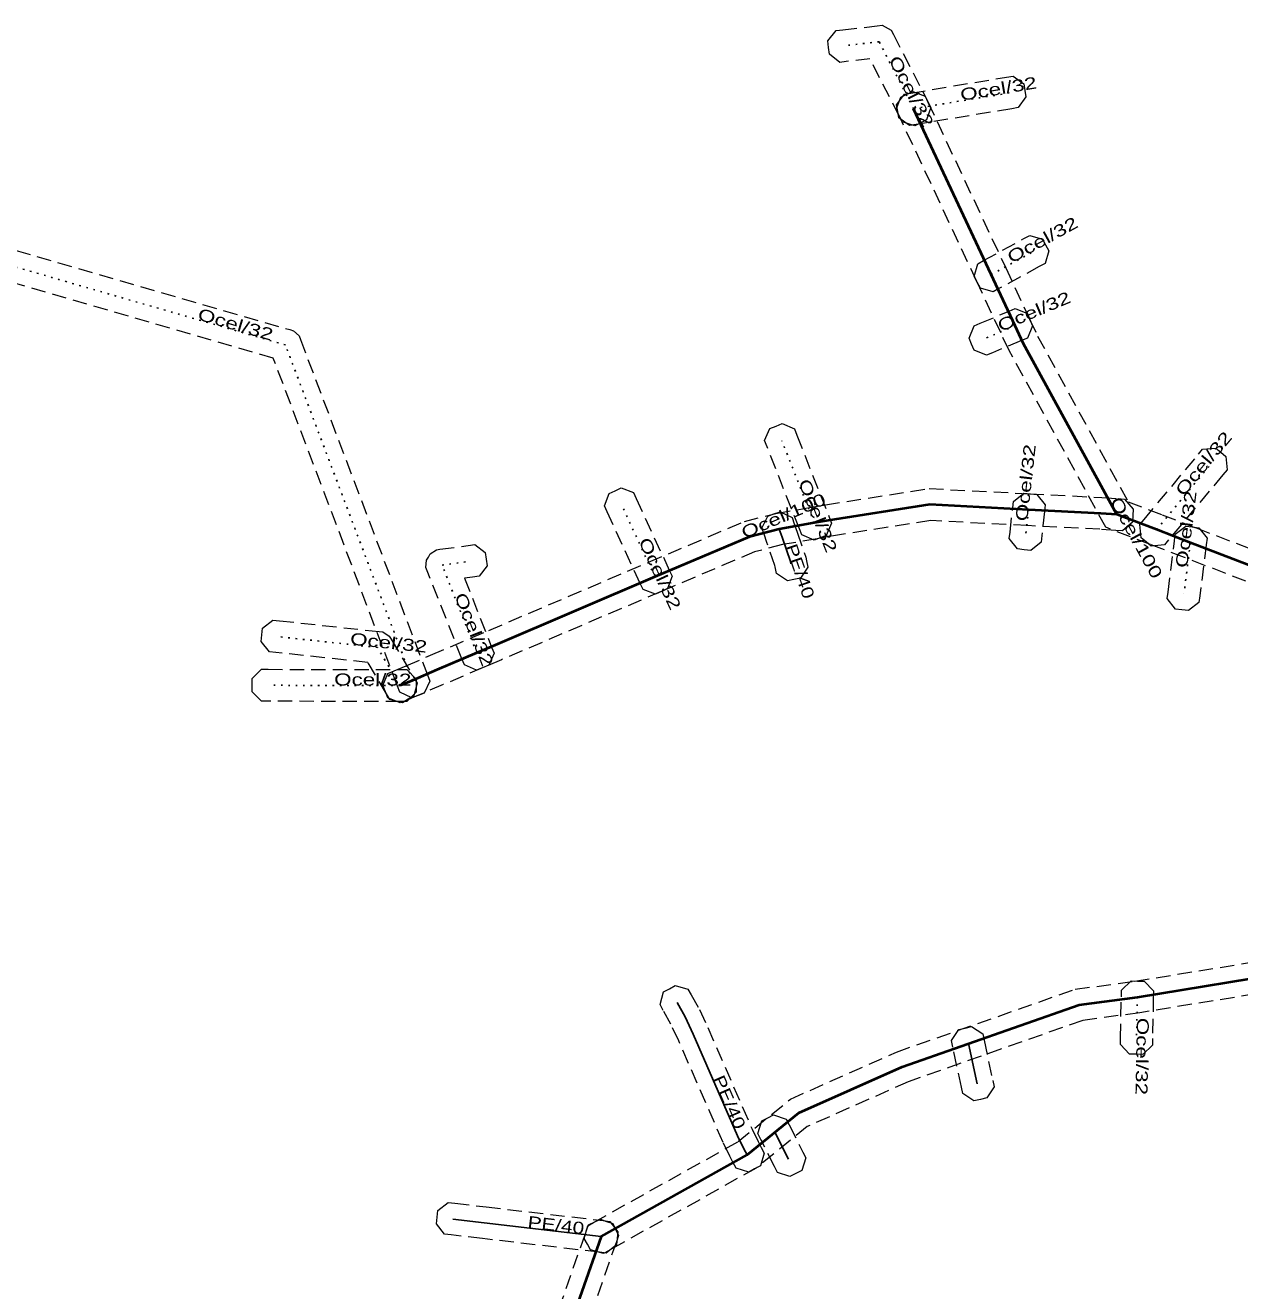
# Model space of a CAD drawing. Extents: x -583333 to -583115, y -1209681 to -1209498.
# Drawn here: x -583255.9 to -583179.8, y -1209577.1 to -1209497.9 of the extents above; entities that cross this region are included whole.
import ezdxf

# ---------------------------------------------------------------- set-up
doc = ezdxf.new("R2010")
doc.units = 0
doc.header["$LTSCALE"] = 0.3
doc.linetypes.add('DOTTED', pattern=[1.5, 0.3, -1.2])
doc.linetypes.add('MEDIUM_DASHED', pattern=[4.5, 3, -1.5])
for name, color, linetype, lineweight in [('1', 7, 'MEDIUM_DASHED', 13), ('14', 7, 'Continuous', 40), ('15', 7, 'Continuous', 25), ('18', 7, 'DOTTED', 25), ('51', 7, 'MEDIUM_DASHED', 13)]:
    doc.layers.add(name, color=color, linetype=linetype, lineweight=lineweight)
doc.layers.add('20', color=7, linetype='Continuous')

msp = doc.modelspace()

# ---------------------------------------------------------------- linework, layer by layer
at = {"layer": '1'}
for points in [[(-583200.941, -1209503.915), (-583201.13, -1209503.546), (-583202.964, -1209499.963), (-583204.446, -1209500.133), (-583204.857, -1209500.181), (-583205.506, -1209499.666), (-583205.553, -1209499.254), (-583205.601, -1209498.843), (-583205.086, -1209498.194), (-583204.674, -1209498.147), (-583202.504, -1209497.897), (-583202.194, -1209497.861), (-583201.643, -1209498.156), (-583201.5, -1209498.434), (-583199.35, -1209502.634), (-583199.161, -1209503.003), (-583199.415, -1209503.791), (-583199.784, -1209503.98), (-583200.153, -1209504.169)], [(-583200.812, -1209502.171), (-583200.403, -1209502.103), (-583194.413, -1209501.113), (-583194.004, -1209501.045), (-583193.331, -1209501.528), (-583193.263, -1209501.937), (-583193.195, -1209502.346), (-583193.678, -1209503.019), (-583194.087, -1209503.087), (-583200.077, -1209504.077), (-583200.486, -1209504.145), (-583201.159, -1209503.662), (-583201.227, -1209503.253), (-583201.295, -1209502.844)], [(-583232.408, -1209539.651), (-583232.555, -1209539.264), (-583240.332, -1209518.712), (-583272.551, -1209509.395), (-583272.949, -1209509.28), (-583273.349, -1209508.554), (-583273.234, -1209508.156), (-583273.119, -1209507.758), (-583272.393, -1209507.358), (-583271.995, -1209507.473), (-583239.296, -1209516.929), (-583239.069, -1209516.995), (-583238.723, -1209517.315), (-583238.639, -1209517.536), (-583230.685, -1209538.556), (-583230.538, -1209538.943), (-583230.879, -1209539.698), (-583231.266, -1209539.845), (-583231.653, -1209539.992)], [(-583196.213, -1209512.8), (-583195.849, -1209512.602), (-583193.319, -1209511.222), (-583192.955, -1209511.024), (-583192.16, -1209511.257), (-583191.962, -1209511.621), (-583191.764, -1209511.985), (-583191.997, -1209512.78), (-583192.361, -1209512.978), (-583194.891, -1209514.358), (-583195.255, -1209514.556), (-583196.05, -1209514.323), (-583196.248, -1209513.959), (-583196.446, -1209513.595)], [(-583193.101, -1209517.452), (-583193.483, -1209517.612), (-583195.293, -1209518.372), (-583195.675, -1209518.532), (-583196.442, -1209518.219), (-583196.602, -1209517.837), (-583196.762, -1209517.455), (-583196.449, -1209516.688), (-583196.067, -1209516.528), (-583194.257, -1209515.768), (-583193.875, -1209515.608), (-583193.108, -1209515.921), (-583192.948, -1209516.303), (-583192.788, -1209516.685)], [(-583207.228, -1209529.792), (-583207.38, -1209529.407), (-583209.41, -1209524.267), (-583209.562, -1209523.882), (-583209.232, -1209523.122), (-583208.847, -1209522.97), (-583208.462, -1209522.818), (-583207.702, -1209523.148), (-583207.55, -1209523.533), (-583205.52, -1209528.673), (-583205.368, -1209529.058), (-583205.698, -1209529.818), (-583206.083, -1209529.97), (-583206.468, -1209530.122)], [(-583186.063, -1209529.138), (-583185.798, -1209528.82), (-583182.398, -1209524.74), (-583182.133, -1209524.422), (-583181.308, -1209524.347), (-583180.99, -1209524.612), (-583180.672, -1209524.877), (-583180.597, -1209525.702), (-583180.862, -1209526.02), (-583184.262, -1209530.1), (-583184.527, -1209530.418), (-583185.352, -1209530.493), (-583185.67, -1209530.228), (-583185.988, -1209529.963)], [(-583187.157, -1209529.537), (-583187.57, -1209529.508), (-583188.56, -1209529.438), (-583193.081, -1209529.209), (-583199.158, -1209528.894), (-583205.427, -1209529.877), (-583206.279, -1209530.025), (-583208.44, -1209530.398), (-583210.188, -1209530.85), (-583216.048, -1209533.34), (-583226.048, -1209537.61), (-583227.197, -1209538.1), (-583229.695, -1209539.169), (-583231.23, -1209539.831), (-583232.006, -1209540.153), (-583232.389, -1209540.312), (-583233.154, -1209539.996), (-583233.313, -1209539.614), (-583233.472, -1209539.231), (-583233.156, -1209538.466), (-583232.774, -1209538.307), (-583232.01, -1209537.989), (-583230.485, -1209537.331), (-583227.983, -1209536.26), (-583226.832, -1209535.77), (-583216.832, -1209531.5), (-583210.832, -1209528.95), (-583208.86, -1209528.442), (-583206.621, -1209528.055), (-583205.753, -1209527.903), (-583199.262, -1209526.886), (-583192.979, -1209527.211), (-583188.44, -1209527.442), (-583187.43, -1209527.512), (-583187.017, -1209527.541), (-583186.473, -1209528.167), (-583186.502, -1209528.58), (-583186.531, -1209528.993)], [(-583217.174, -1209533.215), (-583217.348, -1209532.839), (-583219.418, -1209528.349), (-583219.592, -1209527.973), (-583219.305, -1209527.196), (-583218.929, -1209527.022), (-583218.553, -1209526.848), (-583217.776, -1209527.135), (-583217.602, -1209527.511), (-583215.532, -1209532.001), (-583215.358, -1209532.377), (-583215.645, -1209533.154), (-583216.021, -1209533.328), (-583216.397, -1209533.502)], [(-583191.99, -1209527.91), (-583192.036, -1209528.322), (-583192.206, -1209529.832), (-583192.252, -1209530.244), (-583192.9, -1209530.76), (-583193.312, -1209530.714), (-583193.724, -1209530.668), (-583194.24, -1209530.02), (-583194.194, -1209529.608), (-583194.024, -1209528.098), (-583193.978, -1209527.686), (-583193.33, -1209527.17), (-583192.918, -1209527.216), (-583192.506, -1209527.262)], [(-583207.84, -1209528.702), (-583207.705, -1209529.093), (-583207.525, -1209529.614), (-583206.983, -1209531.188), (-583206.939, -1209531.404), (-583206.858, -1209531.81), (-583207.318, -1209532.499), (-583207.724, -1209532.581), (-583208.13, -1209532.662), (-583208.819, -1209532.202), (-583208.901, -1209531.796), (-583208.917, -1209531.712), (-583209.415, -1209530.266), (-583209.595, -1209529.747), (-583209.73, -1209529.356), (-583209.368, -1209528.61), (-583208.977, -1209528.475), (-583208.586, -1209528.34)], [(-583181.857, -1209529.993), (-583181.908, -1209530.404), (-583182.308, -1209533.614), (-583182.359, -1209534.025), (-583183.013, -1209534.533), (-583183.424, -1209534.482), (-583183.835, -1209534.431), (-583184.343, -1209533.777), (-583184.292, -1209533.366), (-583183.892, -1209530.156), (-583183.841, -1209529.745), (-583183.187, -1209529.237), (-583182.776, -1209529.288), (-583182.365, -1209529.339)], [(-583228.368, -1209537.932), (-583228.52, -1209537.547), (-583230.69, -1209532.047), (-583230.775, -1209531.833), (-583230.739, -1209531.373), (-583230.623, -1209531.174), (-583230.507, -1209530.975), (-583230.123, -1209530.72), (-583229.894, -1209530.689), (-583228.124, -1209530.449), (-583227.714, -1209530.393), (-583227.055, -1209530.896), (-583226.999, -1209531.306), (-583226.943, -1209531.716), (-583227.446, -1209532.375), (-583227.856, -1209532.431), (-583228.362, -1209532.5), (-583226.66, -1209536.813), (-583226.508, -1209537.198), (-583226.838, -1209537.958), (-583227.223, -1209538.11), (-583227.608, -1209538.262)], [(-583233.038, -1209540.097), (-583233.25, -1209539.741), (-583234.415, -1209537.78), (-583240.168, -1209537.154), (-583240.58, -1209537.109), (-583241.099, -1209536.464), (-583241.054, -1209536.052), (-583241.009, -1209535.64), (-583240.364, -1209535.121), (-583239.952, -1209535.166), (-583233.702, -1209535.846), (-583233.467, -1209535.871), (-583233.07, -1209536.126), (-583232.95, -1209536.329), (-583231.53, -1209538.719), (-583231.319, -1209539.075), (-583231.523, -1209539.878), (-583231.879, -1209540.09), (-583232.235, -1209540.301)], [(-583231.978, -1209540.231), (-583232.392, -1209540.23), (-583240.662, -1209540.21), (-583241.076, -1209540.209), (-583241.661, -1209539.622), (-583241.66, -1209539.208), (-583241.659, -1209538.794), (-583241.072, -1209538.209), (-583240.658, -1209538.21), (-583232.388, -1209538.23), (-583231.974, -1209538.231), (-583231.389, -1209538.818), (-583231.39, -1209539.232), (-583231.391, -1209539.646)], [(-583211.352, -1209569.463), (-583211.545, -1209569.096), (-583211.752, -1209568.702), (-583212.168, -1209567.849), (-583214.941, -1209561.482), (-583215.43, -1209560.437), (-583215.912, -1209559.58), (-583216.115, -1209559.219), (-583215.891, -1209558.421), (-583215.53, -1209558.218), (-583215.169, -1209558.015), (-583214.371, -1209558.239), (-583214.168, -1209558.6), (-583213.65, -1209559.523), (-583213.119, -1209560.658), (-583210.352, -1209567.011), (-583209.968, -1209567.798), (-583209.775, -1209568.164), (-583209.582, -1209568.531), (-583209.827, -1209569.322), (-583210.194, -1209569.515), (-583210.561, -1209569.708)], [(-583185.212, -1209558.345), (-583185.22, -1209558.759), (-583185.27, -1209561.349), (-583185.278, -1209561.763), (-583185.875, -1209562.338), (-583186.289, -1209562.33), (-583186.703, -1209562.322), (-583187.278, -1209561.725), (-583187.27, -1209561.311), (-583187.22, -1209558.721), (-583187.212, -1209558.307), (-583186.615, -1209557.732), (-583186.201, -1209557.74), (-583185.787, -1209557.748)], [(-583229.375, -1209571.609), (-583228.963, -1209571.657), (-583227.003, -1209571.887), (-583219.673, -1209572.747), (-583219.262, -1209572.795), (-583218.749, -1209573.445), (-583218.797, -1209573.857), (-583218.845, -1209574.268), (-583219.495, -1209574.781), (-583219.907, -1209574.733), (-583227.237, -1209573.873), (-583229.197, -1209573.643), (-583229.608, -1209573.595), (-583230.121, -1209572.945), (-583230.073, -1209572.533), (-583230.025, -1209572.122)], [(-583218.709, -1209573.68), (-583218.846, -1209574.071), (-583220.99, -1209580.183), (-583222.045, -1209583.616), (-583226.179, -1209600.567), (-583228.63, -1209610.589), (-583226.903, -1209621.007), (-583226.835, -1209621.415), (-583227.318, -1209622.089), (-583227.727, -1209622.157), (-583228.135, -1209622.225), (-583228.809, -1209621.742), (-583228.877, -1209621.333), (-583230.67, -1209610.511), (-583228.121, -1209600.093), (-583223.975, -1209583.084), (-583222.89, -1209579.557), (-583220.734, -1209573.409), (-583220.597, -1209573.018), (-583219.85, -1209572.659), (-583219.459, -1209572.796), (-583219.068, -1209572.933)]]:
    msp.add_lwpolyline(points, close=True, dxfattribs=at)
for points in [[(-583173.121, -1209535.11), (-583183.259, -1209531.213), (-583185.389, -1209530.393), (-583188.202, -1209529.312), (-583194.253, -1209518.232), (-583194.776, -1209517.114), (-583196.276, -1209513.904), (-583201.145, -1209503.514), (-583201.321, -1209503.139), (-583201.039, -1209502.361), (-583200.664, -1209502.185), (-583200.289, -1209502.009), (-583199.511, -1209502.291), (-583199.335, -1209502.666), (-583194.464, -1209513.056), (-583192.964, -1209516.266), (-583192.467, -1209517.328), (-583186.798, -1209527.708), (-583184.671, -1209528.527), (-583182.541, -1209529.347), (-583172.179, -1209533.33)], [(-583176.148, -1209558.11), (-583186.073, -1209559.729), (-583189.635, -1209560.207), (-583200.571, -1209564.05), (-583206.895, -1209566.858), (-583210.096, -1209569.46), (-583219.302, -1209574.613), (-583219.663, -1209574.815), (-583220.46, -1209574.59), (-583220.663, -1209574.228), (-583220.865, -1209573.867), (-583220.64, -1209573.07), (-583220.278, -1209572.867), (-583211.224, -1209567.8), (-583207.951, -1209565.138), (-583201.309, -1209562.19), (-583190.105, -1209558.253), (-583186.367, -1209557.751), (-583176.432, -1209556.13)]]:
    msp.add_lwpolyline(points, dxfattribs=at)
at = {"layer": '14'}
for points in [[(-583163.51, -1209538.98), (-583165.39, -1209539.26), (-583166.84, -1209538.25), (-583172.65, -1209534.22), (-583182.9, -1209530.28), (-583185.03, -1209529.46), (-583187.5, -1209528.51), (-583193.36, -1209517.78), (-583193.87, -1209516.69), (-583195.37, -1209513.48), (-583200.24, -1209503.09)], [(-583187.5, -1209528.51), (-583188.5, -1209528.44), (-583193.03, -1209528.21), (-583199.21, -1209527.89), (-583205.59, -1209528.89), (-583206.45, -1209529.04), (-583208.65, -1209529.42), (-583210.51, -1209529.9), (-583216.44, -1209532.42), (-583226.44, -1209536.69), (-583227.59, -1209537.18), (-583230.09, -1209538.25), (-583231.62, -1209538.91), (-583232.39, -1209539.23)], [(-583219.79, -1209573.74), (-583210.66, -1209568.63), (-583207.423, -1209565.998), (-583200.94, -1209563.12), (-583189.87, -1209559.23), (-583186.22, -1209558.74), (-583176.29, -1209557.12), (-583175, -1209556.96), (-583169.37, -1209556.21), (-583159.86, -1209554.61), (-583158.9, -1209554.46), (-583146.71, -1209551.46), (-583144.88, -1209551.01), (-583130.19, -1209547.39), (-583126.43, -1209546.47), (-583122.4, -1209545.37), (-583115.415, -1209543.463)], [(-583219.79, -1209573.74), (-583221.94, -1209579.87), (-583223.01, -1209583.35), (-583227.15, -1209600.33), (-583229.65, -1209610.55), (-583227.89, -1209621.17)]]:
    msp.add_lwpolyline(points, dxfattribs=at)
at = {"layer": '14', "lineweight": 25}
for points in [[(-583208.65, -1209529.42), (-583208.47, -1209529.94), (-583207.95, -1209531.45), (-583207.92, -1209531.6)], [(-583210.66, -1209568.63), (-583210.86, -1209568.25), (-583211.26, -1209567.43), (-583214.03, -1209561.07), (-583214.54, -1209559.98), (-583215.04, -1209559.09)], [(-583229.08, -1209572.65), (-583227.12, -1209572.88), (-583219.79, -1209573.74)]]:
    msp.add_lwpolyline(points, dxfattribs=at)
at = {"layer": '15'}
for p, q in [((-583196.794, -1209561.663), (-583196.256, -1209564.173)), ((-583208.915, -1209567.211), (-583208.057, -1209568.905))]:
    msp.add_line(p, q, dxfattribs=at)
at = {"layer": '18'}
for p, q in [((-583200.24, -1209503.09), (-583194.25, -1209502.1)), ((-583195.37, -1209513.48), (-583192.84, -1209512.1)), ((-583193.87, -1209516.69), (-583195.68, -1209517.45)), ((-583206.45, -1209529.04), (-583208.48, -1209523.9)), ((-583185.03, -1209529.46), (-583181.63, -1209525.38)), ((-583216.44, -1209532.42), (-583218.51, -1209527.93)), ((-583193.03, -1209528.21), (-583193.2, -1209529.72)), ((-583182.9, -1209530.28), (-583183.3, -1209533.49)), ((-583232.39, -1209539.23), (-583240.66, -1209539.21)), ((-583186.22, -1209558.74), (-583186.27, -1209561.33))]:
    msp.add_line(p, q, dxfattribs=at)
for points in [[(-583200.24, -1209503.09), (-583202.39, -1209498.89), (-583204.56, -1209499.14)], [(-583231.62, -1209538.91), (-583239.574, -1209517.89), (-583272.273, -1209508.434)], [(-583227.59, -1209537.18), (-583229.76, -1209531.68), (-583227.99, -1209531.44)], [(-583232.39, -1209539.23), (-583233.81, -1209536.84), (-583240.06, -1209536.16)]]:
    msp.add_lwpolyline(points, dxfattribs=at)
at = {"layer": '51'}
for points in [[(-583195.903, -1209561.048), (-583195.816, -1209561.453), (-583195.278, -1209563.963), (-583195.191, -1209564.368), (-583195.641, -1209565.064), (-583196.046, -1209565.151), (-583196.451, -1209565.238), (-583197.147, -1209564.788), (-583197.234, -1209564.383), (-583197.772, -1209561.873), (-583197.859, -1209561.468), (-583197.409, -1209560.772), (-583197.004, -1209560.685), (-583196.599, -1209560.598)], [(-583208.21, -1209566.39), (-583208.023, -1209566.759), (-583207.165, -1209568.453), (-583206.978, -1209568.822), (-583207.236, -1209569.61), (-583207.605, -1209569.797), (-583207.974, -1209569.984), (-583208.762, -1209569.726), (-583208.949, -1209569.357), (-583209.807, -1209567.663), (-583209.994, -1209567.294), (-583209.736, -1209566.506), (-583209.367, -1209566.319), (-583208.998, -1209566.132)]]:
    msp.add_lwpolyline(points, close=True, dxfattribs=at)

# ---------------------------------------------------------------- texts
at = {"layer": '20'}
for s, rotation, width, p in [('Ocel/32', 297.108, 1.4, (-583201.812, -1209500.018)), ('Ocel/32', 9.385, 1.4, (-583197.245, -1209502.595)), ('Ocel/32', 28.61, 1.4, (-583194.105, -1209512.79)), ('Ocel/32', 22.777, 1.4, (-583194.775, -1209517.07)), ('Ocel/32', 343.871, 1.4, (-583245.128, -1209516.284)), ('Ocel/32', 50.194, 1.4, (-583183.33, -1209527.42)), ('Ocel/32', 83.577, 1.4, (-583193.115, -1209528.965)), ('Ocel/32', 291.551, 1.4, (-583207.465, -1209526.47)), ('Ocel/32', 82.897, 1.4, (-583183.1, -1209531.885)), ('Ocel/100', 23.023, 1.4, (-583210.821, -1209530.032)), ('Ocel/100', 298.64, 1.4, (-583187.955, -1209527.677)), ('Ocel/32', 294.751, 1.4, (-583217.475, -1209530.175)), ('PE/40', 289.002, 1.3, (-583208.274, -1209530.507)), ('Ocel/32', 291.531, 1.4, (-583229.003, -1209533.599)), ('Ocel/32', 353.791, 1.4, (-583235.553, -1209536.65)), ('Ocel/32', 359.861, 1.4, (-583236.525, -1209539.22)), ('Ocel/32', 268.894, 1.4, (-583186.245, -1209560.035)), ('PE/40', 293.535, 1.3, (-583212.821, -1209563.845)), ('PE/40', 353.308, 1.3, (-583224.435, -1209573.195))]:
    msp.add_text(s, height=0.75, rotation=rotation, dxfattribs=dict(at, width=width)).set_placement(p)

doc.saveas('drawing.dxf')
